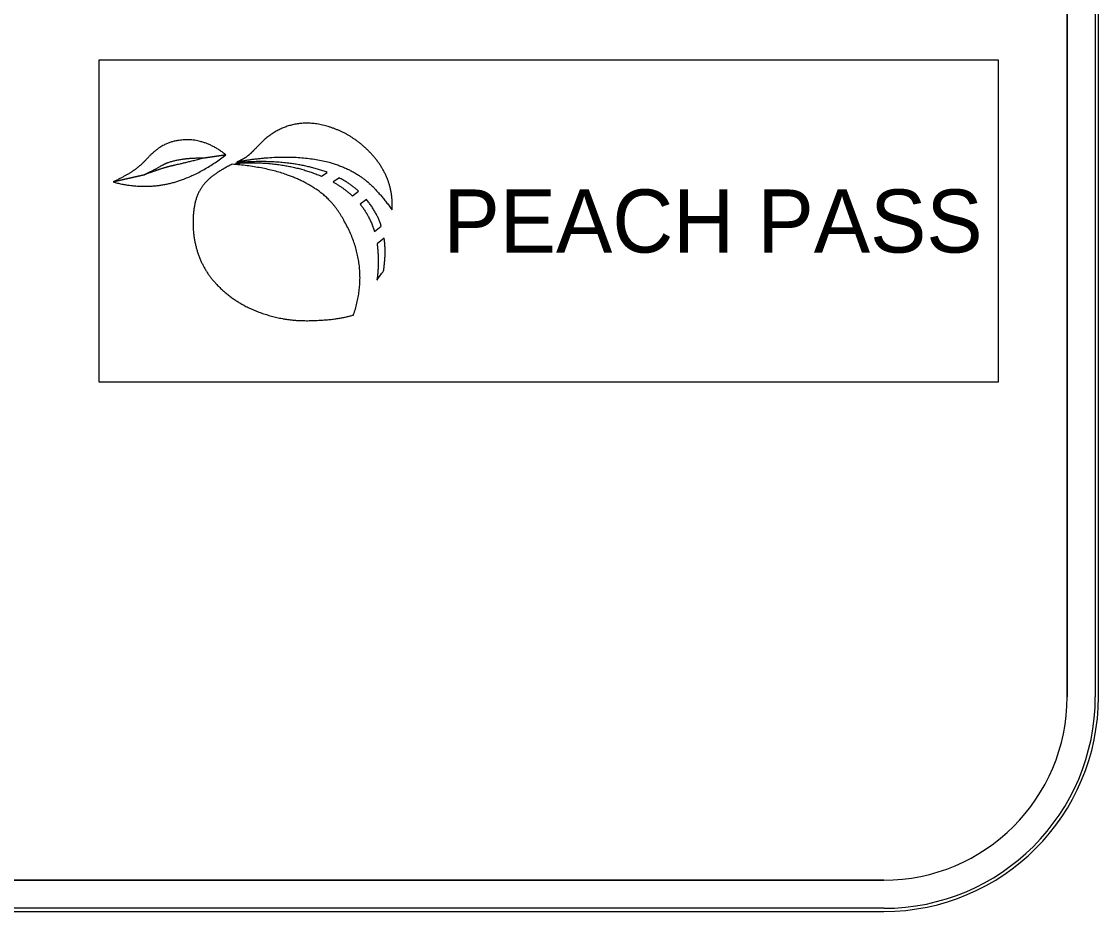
# Model space of a CAD drawing. Extents: x 17890459 to 17890580, y 17897938 to 17898017.
# Drawn here: x 17890502.24 to 17890507.25, y 17898000.75 to 17898004.89 of the extents above; entities that cross this region are included whole.
import ezdxf

# ---------------------------------------------------------------- set-up
doc = ezdxf.new("R2010")
doc.units = 0
for name, color, linetype in [('GSBWFill', 7, 'Continuous'), ('GSColorFill', 7, 'Continuous'), ('GSOutline', 7, 'Continuous'), ('Logo_dp', 7, 'Continuous')]:
    doc.layers.add(name, color=color, linetype=linetype)

msp = doc.modelspace()

# ---------------------------------------------------------------- linework, layer by layer
at = {"layer": 'GSBWFill'}
for p, q in [((17890507.1053, 17898011.7505), (17890507.1053, 17898001.7505)), ((17890507.2511, 17898001.7505), (17890507.2511, 17898011.7505)), ((17890506.2511, 17898000.8963), (17890493.7526, 17898000.8963)), ((17890493.7526, 17898000.7505), (17890506.2511, 17898000.7505))]:
    msp.add_line(p, q, dxfattribs=at)
for radius in [1, 0.8542]:
    msp.add_arc((17890506.2511, 17898001.7505), radius, 270, 0, dxfattribs=at)
at = {"layer": 'GSColorFill'}
for p, q in [((17890507.1053, 17898011.7505), (17890507.1053, 17898001.7505)), ((17890507.2365, 17898011.7505), (17890507.2365, 17898001.7505)), ((17890507.2511, 17898001.7505), (17890507.2511, 17898011.7505)), ((17890507.2511, 17898001.7505), (17890507.2511, 17898011.7505)), ((17890507.2511, 17898001.7505), (17890507.2511, 17898011.7505)), ((17890506.2511, 17898000.8963), (17890493.7526, 17898000.8963)), ((17890493.7511, 17898000.7505), (17890506.2511, 17898000.7505)), ((17890506.2511, 17898000.7651), (17890493.7513, 17898000.7651)), ((17890493.7513, 17898000.7505), (17890506.2511, 17898000.7505)), ((17890493.7526, 17898000.7505), (17890506.2511, 17898000.7505))]:
    msp.add_line(p, q, dxfattribs=at)
msp.add_lwpolyline([(17890502.5969, 17898004.7156), (17890506.7842, 17898004.7156), (17890506.7842, 17898003.2156), (17890502.5969, 17898003.2156)], close=True, dxfattribs=at)
for radius in [1, 1, 0.8542, 1, 0.9854]:
    msp.add_arc((17890506.2511, 17898001.7505), radius, 270, 0, dxfattribs=at)
at = {"layer": 'GSOutline'}
for p, q in [((17890507.1053, 17898001.7505), (17890507.1053, 17898011.7505)), ((17890507.2511, 17898001.7505), (17890507.2511, 17898011.7505)), ((17890493.7511, 17898000.8963), (17890506.2511, 17898000.8963)), ((17890493.7511, 17898000.7505), (17890506.2511, 17898000.7505))]:
    msp.add_line(p, q, dxfattribs=at)
for radius in [1, 0.8542]:
    msp.add_arc((17890506.2511, 17898001.7505), radius, 270, 0, dxfattribs=at)
at = {"layer": 'Logo_dp'}
for p, q in [((17890503.0912, 17898004.2593), (17890503.1879, 17898004.2735)), ((17890503.1879, 17898004.2735), (17890503.0912, 17898004.2593)), ((17890503.2386, 17898004.237), (17890503.2328, 17898004.2341)), ((17890503.6328, 17898004.1741), (17890503.6599, 17898004.1922)), ((17890502.6618, 17898004.1478), (17890502.8067, 17898004.1806)), ((17890502.8067, 17898004.1806), (17890502.6618, 17898004.1478)), ((17890503.7162, 17898004.1666), (17890503.6875, 17898004.1474)), ((17890503.777, 17898004.0821), (17890503.8057, 17898004.1039)), ((17890503.842, 17898004.0654), (17890503.8129, 17898004.0433)), ((17890503.879, 17898003.9166), (17890503.9109, 17898003.9421)), ((17890503.9245, 17898003.8858), (17890503.8917, 17898003.859))]:
    msp.add_line(p, q, dxfattribs=at)
msp.add_arc((17890503.084, 17898004.2942), 1.0078, 323.2218, 326.1982, dxfattribs=at)
for points in [[(17890503.498, 17898004.4137), (17890503.414, 17898004.3931), (17890503.347, 17898004.325)], [(17890503.6914, 17898004.3962), (17890503.5902, 17898004.4348), (17890503.498, 17898004.4137)], [(17890503.8836, 17898004.2571), (17890503.8033, 17898004.3544), (17890503.6914, 17898004.3962)], [(17890503.1879, 17898004.2735), (17890503.0794, 17898004.3603), (17890502.9625, 17898004.3401)], [(17890502.9625, 17898004.3401), (17890502.888, 17898004.3294), (17890502.8211, 17898004.257)], [(17890503.347, 17898004.325), (17890503.3201, 17898004.297), (17890503.3086, 17898004.2859)], [(17890502.8211, 17898004.257), (17890502.7893, 17898004.221), (17890502.7555, 17898004.1991)], [(17890502.8399, 17898004.1281), (17890503.0084, 17898004.1368), (17890503.1879, 17898004.2735)], [(17890502.8895, 17898004.2241), (17890502.9209, 17898004.244), (17890502.9828, 17898004.2533)], [(17890503.0912, 17898004.2593), (17890502.9656, 17898004.2288), (17890502.9393, 17898004.2228)], [(17890502.9828, 17898004.2533), (17890503.0251, 17898004.2605), (17890503.0912, 17898004.2593)], [(17890503.6599, 17898004.1922), (17890503.4784, 17898004.2584), (17890503.2386, 17898004.237)], [(17890503.2402, 17898004.2413), (17890503.3072, 17898004.2546), (17890503.3825, 17898004.2605)], [(17890503.2715, 17898004.2565), (17890503.271, 17898004.2559), (17890503.2402, 17898004.2413)], [(17890503.3086, 17898004.2859), (17890503.2894, 17898004.2665), (17890503.2715, 17898004.2565)], [(17890503.3825, 17898004.2605), (17890503.6524, 17898004.2795), (17890503.8088, 17898004.1768)], [(17890503.9614, 17898004.0177), (17890503.9695, 17898004.1503), (17890503.8836, 17898004.2571)], [(17890502.7555, 17898004.1991), (17890502.7161, 17898004.1723), (17890502.6618, 17898004.1478)], [(17890502.8067, 17898004.1806), (17890502.8367, 17898004.1949), (17890502.8895, 17898004.2241)], [(17890502.8683, 17898004.2023), (17890502.846, 17898004.1952), (17890502.8067, 17898004.1806)], [(17890502.9393, 17898004.2228), (17890502.9102, 17898004.217), (17890502.8683, 17898004.2023)], [(17890503.2164, 17898004.2296), (17890503.107, 17898004.1763), (17890503.0739, 17898004.12)], [(17890503.6079, 17898004.1132), (17890503.4622, 17898004.2125), (17890503.2164, 17898004.2296)], [(17890503.2328, 17898004.2341), (17890503.4525, 17898004.2503), (17890503.6328, 17898004.1741)], [(17890502.6618, 17898004.1478), (17890502.7455, 17898004.1234), (17890502.8399, 17898004.1281)], [(17890503.6875, 17898004.1474), (17890503.7372, 17898004.1188), (17890503.777, 17898004.0821)], [(17890503.8057, 17898004.1039), (17890503.7727, 17898004.135), (17890503.7162, 17898004.1666)], [(17890503.8088, 17898004.1768), (17890503.8765, 17898004.1347), (17890503.9614, 17898004.0177)], [(17890503.0739, 17898004.12), (17890503.0264, 17898004.0544), (17890503.0364, 17898003.9118)], [(17890503.7366, 17898003.9692), (17890503.6864, 17898004.0623), (17890503.6079, 17898004.1132)], [(17890503.8129, 17898004.0433), (17890503.8585, 17898003.9887), (17890503.879, 17898003.9166)], [(17890503.9109, 17898003.9421), (17890503.8903, 17898004.0078), (17890503.842, 17898004.0654)], [(17890503.7818, 17898003.5276), (17890503.8599, 17898003.7557), (17890503.7366, 17898003.9692)], [(17890503.0364, 17898003.9118), (17890503.052, 17898003.7695), (17890503.1422, 17898003.673)], [(17890503.8917, 17898003.859), (17890503.9024, 17898003.7743), (17890503.8913, 17898003.6908)], [(17890503.9215, 17898003.7335), (17890503.9349, 17898003.8136), (17890503.9245, 17898003.8858)], [(17890503.1422, 17898003.673), (17890503.2574, 17898003.5484), (17890503.4506, 17898003.5113)], [(17890503.4506, 17898003.5113), (17890503.5232, 17898003.497), (17890503.6274, 17898003.5036)], [(17890503.6274, 17898003.5036), (17890503.7127, 17898003.5081), (17890503.7818, 17898003.5276)]]:
    msp.add_open_spline(points, degree=2, dxfattribs=at)

# ---------------------------------------------------------------- texts
at = {"layer": 'GSColorFill'}
msp.add_text('PEACH PASS', height=0.29376, dxfattribs=at).set_placement((17890504.201, 17898003.8187))

doc.saveas('drawing.dxf')
